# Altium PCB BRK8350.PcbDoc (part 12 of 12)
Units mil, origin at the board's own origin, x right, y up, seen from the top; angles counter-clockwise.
Board outline 9448.82 x 5905.51 mil, 8 copper layers (L1-TOP, L2-GND, L3-SIG, L4-GND, L5-PWR, L6-PWR, L7-GND, L8-BOT), stack 57.69 mil thick; 288 components, 543 nets, 1891 pads, 2032 vias.
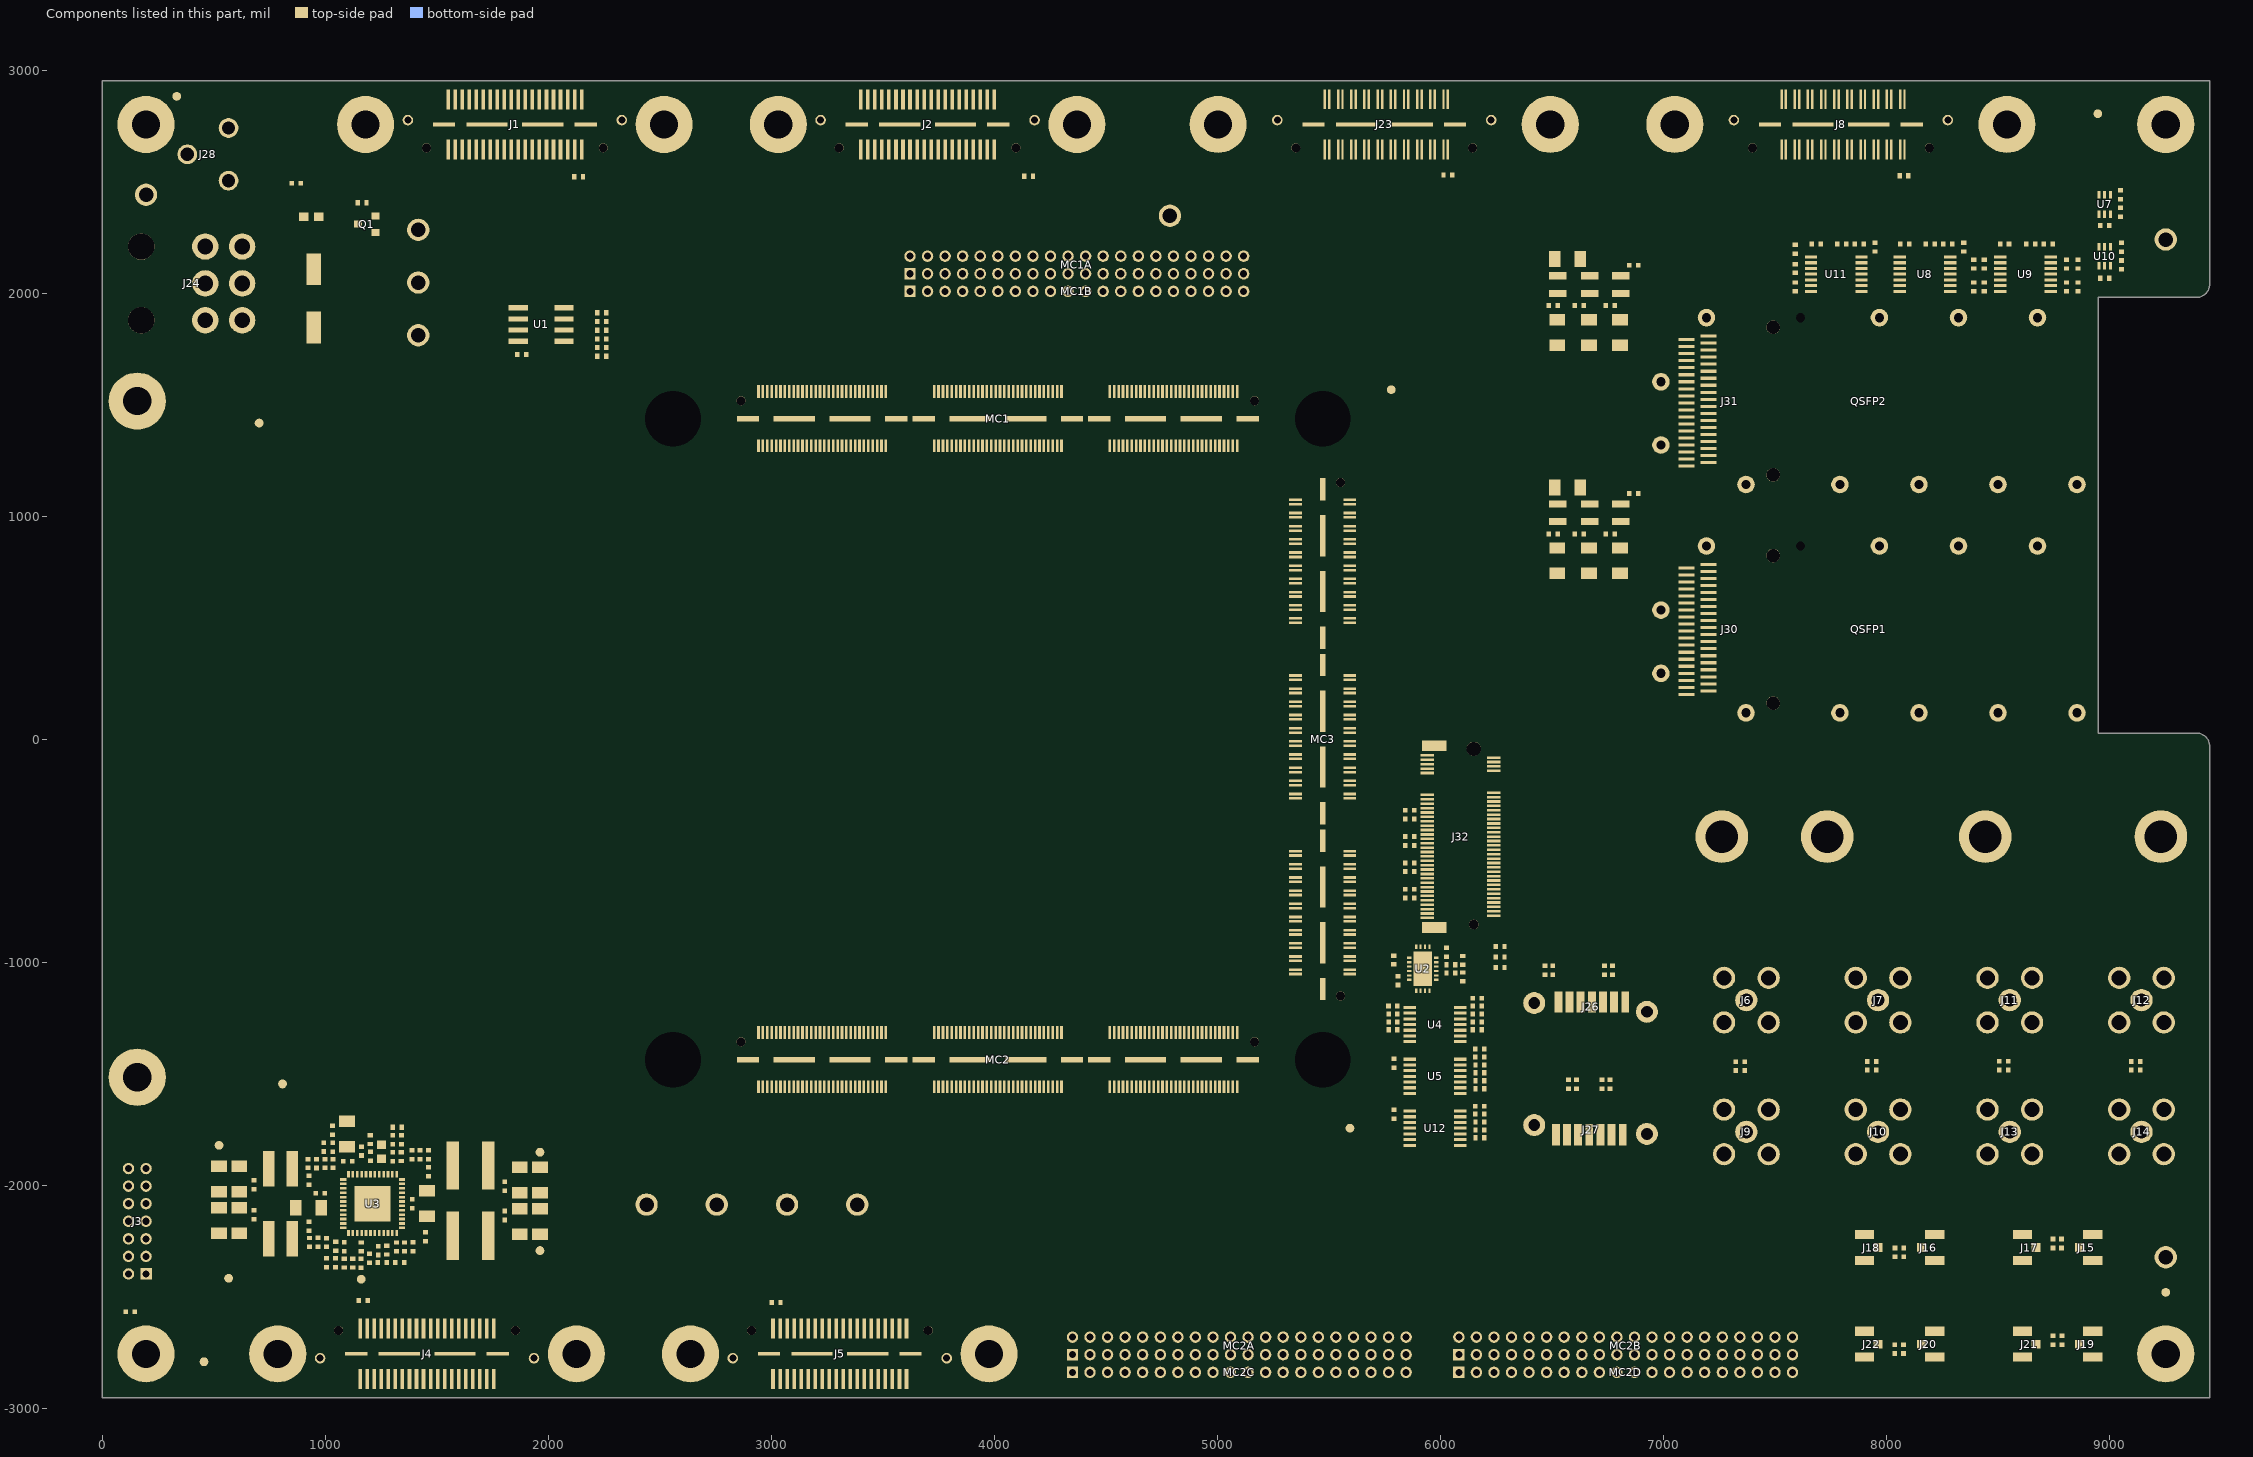
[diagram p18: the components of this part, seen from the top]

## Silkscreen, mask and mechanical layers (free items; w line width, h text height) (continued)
Fab Notes:
  drawing of 156 lines, arcs and shapes, not listed
  text "NOTES: /  / 1. MATERIAL: /    IT-180A or equivalent /    Surface finish: ENIG /    Overall thickness: 93 mils +/-10% /  / 2. Fabricate to IPC-6012 (latest revision), Class 2 /  / 3. SOLDER RESIST: Glossy blue LPI applied over bare copper or gold/nickel plating /  / 4. SILKSCREEN: White /  / 5. LOT CODE IDENTIFICATION: /    Supplier must add identifier and lot code date to silkscreen. /    LOT CODE DATE FORMAT: YYWW (YY = 2-digit year, WW = 2-digit week) /  / 6. Drill sizes are finished size after plating /  / 7. 100% electrical bare board test required for continuity /  / 8. IMPEDANCE CONTROL: /    See Layer Stackup Table on this drawing and refer to '.Part_Number'-PCBStackup.pdf /  / 9. PANELIZATION: /    1 pieces per array /    Tab routing required. Tab locations indicated by ::: (see Dimensions Gerber layer) /    OUTLINE DIMENSION TOLERANCE: +/-0.127 mm /    0.25-inch rails on all sides /  / 10. POFV: All 10-mil diameter vias must be filled using non-conductive epoxy and plated over. /  / 11. ROHS: Fabricate to meet EU RoHS directive. Supplier must add lead-free marking in silkscreen. /  / 12. UL: Supplier must add UL certification marking (94V-0) in silkscreen. /  / 13. Remove all non-functional pads from internal layers" at -129.92,4185.04 h38
  text "LAYER STACKUP TABLE" at 9901.57,3334.65 h50
  text "S" at 12745.09,3247.32 h68.37
  text "i" at 12772.5,3247.32 h68.37
  text "n" at 12788.16,3247.32 h68.37
  text "g" at 12819.49,3247.32 h68.37
  text "l" at 12846.9,3247.32 h68.37
  text "e" at 12862.57,3247.32 h68.37
  text "-" at 12893.89,3247.32 h68.37
  text "E" at 12913.47,3247.32 h68.37
  text "n" at 12940.88,3247.32 h68.37
  text "d" at 12972.21,3247.32 h68.37
  text "e" at 13003.54,3247.32 h68.37
  text "d" at 13034.87,3247.32 h68.37
  text "D" at 13870.76,3247.32 h68.37
  text "i" at 13906,3247.32 h68.37
  text "f" at 13921.66,3247.32 h68.37
  text "f" at 13941.24,3247.32 h68.37
  text "e" at 13960.82,3247.32 h68.37
  text "r" at 13992.15,3247.32 h68.37
  text "e" at 14011.73,3247.32 h68.37
  text "n" at 14043.06,3247.32 h68.37
  text "t" at 14074.39,3247.32 h68.37
  text "i" at 14093.97,3247.32 h68.37
  text "a" at 14109.63,3247.32 h68.37
  text "l" at 14137.04,3247.32 h68.37
  text "D" at 14195.17,3247.32 h68.37
  text "i" at 14230.41,3247.32 h68.37
  text "f" at 14246.08,3247.32 h68.37
  text "f" at 14265.66,3247.32 h68.37
  text "e" at 14285.24,3247.32 h68.37
  text "r" at 14316.56,3247.32 h68.37
  text "e" at 14336.14,3247.32 h68.37
  text "n" at 14367.47,3247.32 h68.37
  text "t" at 14398.8,3247.32 h68.37
  text "i" at 14418.38,3247.32 h68.37
  text "a" at 14434.04,3247.32 h68.37
  text "l" at 14461.45,3247.32 h68.37
  text "M" at 12022,3171.76 h68.37
  text "a" at 12072.91,3171.76 h68.37
  text "t" at 12104.24,3171.76 h68.37
  text "e" at 12123.81,3171.76 h68.37
  text "r" at 12159.06,3171.76 h68.37
  text "i" at 12182.55,3171.76 h68.37
  text "a" at 12198.22,3171.76 h68.37
  text "l" at 12229.55,3171.76 h68.37
  text "T" at 12842.8,3169 h68.37
  text "r" at 12870.21,3169 h68.37
  text "a" at 12889.79,3169 h68.37
  text "c" at 12917.2,3169 h68.37
  text "e" at 12940.7,3169 h68.37
  text "S" at 13112.49,3169 h68.37
  text "i" at 13139.9,3169 h68.37
  text "n" at 13155.57,3169 h68.37
  text "g" at 13186.9,3169 h68.37
  text "l" at 13214.31,3169 h68.37
  text "e" at 13229.97,3169 h68.37
  text "-" at 13261.3,3169 h68.37
  text "E" at 13280.88,3169 h68.37
  text "n" at 13308.29,3169 h68.37
  text "d" at 13339.62,3169 h68.37
  text "e" at 13370.94,3169 h68.37
  text "d" at 13402.27,3169 h68.37
  text "T" at 13948.93,3169 h68.37
  text "r" at 13976.34,3169 h68.37
  text "a" at 13995.92,3169 h68.37
  text "c" at 14023.33,3169 h68.37
  text "e" at 14046.83,3169 h68.37
  text "T" at 14269.43,3169 h68.37
  text "r" at 14296.84,3169 h68.37
  text "a" at 14316.42,3169 h68.37
  text "c" at 14343.83,3169 h68.37
  text "e" at 14367.33,3169 h68.37
  text "G" at 10626.64,3093.44 h68.37
  text "e" at 10673.63,3093.44 h68.37
  text "r" at 10708.87,3093.44 h68.37
  text "b" at 10732.37,3093.44 h68.37
  text "e" at 10767.61,3093.44 h68.37
  text "r" at 10802.86,3093.44 h68.37
  text "M" at 11263.74,3093.44 h68.37
  text "a" at 11314.64,3093.44 h68.37
  text "t" at 11345.97,3093.44 h68.37
  text "e" at 11365.55,3093.44 h68.37
  text "r" at 11400.79,3093.44 h68.37
  text "i" at 11424.29,3093.44 h68.37
  text "a" at 11439.95,3093.44 h68.37
  text "l" at 11471.28,3093.44 h68.37
  text "M" at 11646.78,3093.44 h68.37
  text "a" at 11697.68,3093.44 h68.37
  text "t" at 11729.01,3093.44 h68.37
  text "e" at 11748.59,3093.44 h68.37
  text "r" at 11783.83,3093.44 h68.37
  text "i" at 11807.33,3093.44 h68.37
  text "a" at 11822.99,3093.44 h68.37
  text "l" at 11854.32,3093.44 h68.37
  text "E" at 11885.65,3093.44 h68.37
  text "r" at 11924.81,3093.44 h68.37
  text "T" at 11990.73,3093.44 h68.37
  text "h" at 12029.89,3093.44 h68.37
  text "i" at 12065.13,3093.44 h68.37
  text "c" at 12080.8,3093.44 h68.37
  text "k" at 12112.13,3093.44 h68.37
  text "n" at 12143.45,3093.44 h68.37
  text "e" at 12178.7,3093.44 h68.37
  text "s" at 12213.94,3093.44 h68.37
  text "s" at 12245.27,3093.44 h68.37
  text "C" at 12408.95,3090.68 h68.37
  text "o" at 12440.28,3090.68 h68.37
  text "p" at 12471.6,3090.68 h68.37
  text "p" at 12502.93,3090.68 h68.37
  text "e" at 12534.26,3090.68 h68.37
  text "r" at 12565.59,3090.68 h68.37
  text "I" at 12772.45,3090.68 h68.37
  text "m" at 12788.11,3090.68 h68.37
  text "p" at 12835.1,3090.68 h68.37
  text "e" at 12866.43,3090.68 h68.37
  text "d" at 12897.76,3090.68 h68.37
  text "a" at 12929.08,3090.68 h68.37
  text "n" at 12956.5,3090.68 h68.37
  text "c" at 12987.82,3090.68 h68.37
  text "e" at 13011.32,3090.68 h68.37
  text "T" at 13128.13,3090.68 h68.37
  text "r" at 13155.54,3090.68 h68.37
  text "a" at 13175.12,3090.68 h68.37
  text "c" at 13202.53,3090.68 h68.37
  text "e" at 13226.03,3090.68 h68.37
  text "W" at 13269.1,3090.68 h68.37
  text "i" at 13323.92,3090.68 h68.37
  text "d" at 13339.59,3090.68 h68.37
  text "t" at 13370.92,3090.68 h68.37
  text "h" at 13390.5,3090.68 h68.37
  text "I" at 13878.57,3090.68 h68.37
  text "m" at 13894.24,3090.68 h68.37
  text "p" at 13941.23,3090.68 h68.37
  text "e" at 13972.56,3090.68 h68.37
  text "d" at 14003.88,3090.68 h68.37
  text "a" at 14035.21,3090.68 h68.37
  text "n" at 14062.62,3090.68 h68.37
  text "c" at 14093.95,3090.68 h68.37
  text "e" at 14117.45,3090.68 h68.37
  text "W" at 14175.63,3090.68 h68.37
  text "i" at 14230.45,3090.68 h68.37
  text "d" at 14246.11,3090.68 h68.37
  text "t" at 14277.44,3090.68 h68.37
  text "h" at 14297.02,3090.68 h68.37
  text "/" at 14328.35,3090.68 h68.37
  text "S" at 14351.84,3090.68 h68.37
  text "p" at 14379.25,3090.68 h68.37
  text "a" at 14410.58,3090.68 h68.37
  text "c" at 14437.99,3090.68 h68.37
  text "e" at 14461.49,3090.68 h68.37
  text "L" at 9876.19,3015.12 h68.37
  text "a" at 9911.44,3015.12 h68.37
  text "y" at 9942.76,3015.12 h68.37
  text "e" at 9970.17,3015.12 h68.37
  text "r" at 10005.42,3015.12 h68.37
  text "L" at 10071.62,3015.12 h68.37
  text "a" at 10106.86,3015.12 h68.37
  text "y" at 10138.19,3015.12 h68.37
  text "e" at 10165.6,3015.12 h68.37
  text "r" at 10200.85,3015.12 h68.37
  text "N" at 10240.01,3015.12 h68.37
  text "a" at 10283.08,3015.12 h68.37
  text "m" at 10314.41,3015.12 h68.37
  text "e" at 10361.4,3015.12 h68.37
  text "L" at 10626.64,3015.12 h68.37
  text "a" at 10661.88,3015.12 h68.37
  text "y" at 10693.21,3015.12 h68.37
  text "e" at 10720.62,3015.12 h68.37
  text "r" at 10755.86,3015.12 h68.37
  text "M" at 10861.15,3015.12 h68.37
  text "a" at 10912.06,3015.12 h68.37
  text "t" at 10943.39,3015.12 h68.37
  text "e" at 10962.97,3015.12 h68.37
  text "r" at 10998.21,3015.12 h68.37
  text "i" at 11021.71,3015.12 h68.37
  text "a" at 11037.37,3015.12 h68.37
  text "l" at 11068.7,3015.12 h68.37
  text "T" at 11100.03,3015.12 h68.37
  text "y" at 11139.19,3015.12 h68.37
  text "p" at 11166.6,3015.12 h68.37
  text "e" at 11201.84,3015.12 h68.37
  text "C" at 11263.74,3015.12 h68.37
  text "o" at 11306.81,3015.12 h68.37
  text "n" at 11342.06,3015.12 h68.37
  text "s" at 11377.3,3015.12 h68.37
  text "t" at 11408.63,3015.12 h68.37
  text "r" at 11428.21,3015.12 h68.37
  text "u" at 11451.7,3015.12 h68.37
  text "c" at 11486.95,3015.12 h68.37
  text "t" at 11518.27,3015.12 h68.37
  text "i" at 11537.85,3015.12 h68.37
  text "o" at 11553.52,3015.12 h68.37
  text "n" at 11588.76,3015.12 h68.37
  text "(" at 11693.68,3015.12 h68.37
  text "1" at 11713.26,3015.12 h68.37
  text "G" at 11760.25,3015.12 h68.37
  text "H" at 11807.24,3015.12 h68.37
  text "z" at 11850.32,3015.12 h68.37
  text ")" at 11881.65,3015.12 h68.37
  text "(" at 12076.72,3015.12 h68.37
  text "m" at 12096.3,3015.12 h68.37
  text "i" at 12143.29,3015.12 h68.37
  text "l" at 12158.96,3015.12 h68.37
  text ")" at 12174.62,3015.12 h68.37
  text "W" at 12354.23,3012.36 h68.37
  text "e" at 12409.05,3012.36 h68.37
  text "i" at 12440.38,3012.36 h68.37
  text "g" at 12456.04,3012.36 h68.37
  text "h" at 12483.46,3012.36 h68.37
  text "t" at 12514.78,3012.36 h68.37
  text "(" at 12546.11,3012.36 h68.37
  text "o" at 12565.69,3012.36 h68.37
  text "z" at 12597.02,3012.36 h68.37
  text ")" at 12620.51,3012.36 h68.37
  text "(" at 12819.35,3012.36 h68.37
  text "o" at 12838.93,3012.36 h68.37
  text "h" at 12870.26,3012.36 h68.37
  text "m" at 12901.58,3012.36 h68.37
  text "s" at 12948.58,3012.36 h68.37
  text ")" at 12972.07,3012.36 h68.37
  text "(" at 13202.39,3012.36 h68.37
  text "m" at 13221.97,3012.36 h68.37
  text "i" at 13268.96,3012.36 h68.37
  text "l" at 13284.62,3012.36 h68.37
  text "s" at 13300.29,3012.36 h68.37
  text ")" at 13323.78,3012.36 h68.37
  text "R" at 13511.17,3012.36 h68.37
  text "e" at 13542.5,3012.36 h68.37
  text "f" at 13573.82,3012.36 h68.37
  text "e" at 13593.4,3012.36 h68.37
  text "r" at 13624.73,3012.36 h68.37
  text "e" at 13644.31,3012.36 h68.37
  text "n" at 13675.64,3012.36 h68.37
  text "c" at 13706.96,3012.36 h68.37
  text "e" at 13730.46,3012.36 h68.37
  text "(" at 13925.48,3012.36 h68.37
  text "o" at 13945.06,3012.36 h68.37
  text "h" at 13976.38,3012.36 h68.37
  text "m" at 14007.71,3012.36 h68.37
  text "s" at 14054.7,3012.36 h68.37
  text ")" at 14078.2,3012.36 h68.37
  text "(" at 14265.52,3012.36 h68.37
  text "m" at 14285.1,3012.36 h68.37
  text "i" at 14332.09,3012.36 h68.37
  text "l" at 14347.76,3012.36 h68.37
  text "s" at 14363.42,3012.36 h68.37
  text ")" at 14386.92,3012.36 h68.37
  text "R" at 14562.57,3012.36 h68.37
  text "e" at 14593.9,3012.36 h68.37
  text "f" at 14625.23,3012.36 h68.37
  text "e" at 14644.81,3012.36 h68.37
  text "r" at 14676.14,3012.36 h68.37
  text "e" at 14695.72,3012.36 h68.37
  text "n" at 14727.04,3012.36 h68.37
  text "c" at 14758.37,3012.36 h68.37
  text "e" at 14781.87,3012.36 h68.37
  text "O" at 10071.62,2901.56 h64.57
  text "v" at 10118.61,2901.56 h64.57
  text "e" at 10146.02,2901.56 h64.57
  text "r" at 10177.35,2901.56 h64.57
  text "l" at 10196.93,2901.56 h64.57
  text "a" at 10208.68,2901.56 h64.57
  text "y" at 10240.01,2901.53 h64.57
  text "T" at 10283.08,2901.56 h64.57
  text "o" at 10318.33,2901.56 h64.57
  text "p" at 10349.65,2901.53 h64.57
  text "G" at 10626.64,2901.56 h64.57
  text "T" at 10669.71,2901.56 h64.57
  text "O" at 10704.96,2901.56 h64.57
  text "S" at 10861.15,2901.56 h64.57
  text "i" at 10900.31,2901.56 h64.57
  text "l" at 10912.06,2901.56 h64.57
  text "k" at 10923.81,2901.56 h64.57
  text "s" at 10951.22,2901.56 h64.57
  text "c" at 10982.55,2901.56 h64.57
  text "r" at 11013.88,2901.56 h64.57
  text "e" at 11033.45,2901.56 h64.57
  text "e" at 11064.78,2901.56 h64.57
  text "n" at 11096.11,2901.56 h64.57
  text "S" at 10071.62,2823.24 h64.57
  text "o" at 10110.78,2823.24 h64.57
  text "l" at 10142.11,2823.24 h64.57
  text "d" at 10153.86,2823.24 h64.57
  text "e" at 10185.18,2823.24 h64.57
  text "r" at 10216.51,2823.24 h64.57
  text "M" at 10251.75,2823.24 h64.57
  text "a" at 10294.83,2823.24 h64.57
  text "s" at 10326.16,2823.24 h64.57
  text "k" at 10357.48,2823.24 h64.57
  text "T" at 10400.56,2823.24 h64.57
  text "o" at 10435.8,2823.24 h64.57
  text "p" at 10467.13,2823.21 h64.57
  text "G" at 10626.64,2823.24 h64.57
  text "T" at 10669.71,2823.24 h64.57
  text "S" at 10704.96,2823.24 h64.57
  text "S" at 10861.15,2823.24 h64.57
  text "o" at 10900.31,2823.24 h64.57
  text "l" at 10931.64,2823.24 h64.57
  text "d" at 10943.39,2823.24 h64.57
  text "e" at 10974.72,2823.24 h64.57
  text "r" at 11006.04,2823.24 h64.57
  text "R" at 11041.29,2823.24 h64.57
  text "e" at 11084.36,2823.24 h64.57
  text "s" at 11115.69,2823.24 h64.57
  text "i" at 11147.02,2823.24 h64.57
  text "s" at 11158.76,2823.24 h64.57
  text "t" at 11190.09,2823.24 h64.57
  text "3" at 11764.03,2820.48 h68.37
  text "." at 11791.45,2820.48 h68.37
  text "5" at 11807.11,2820.48 h68.37
  text "1" at 9876.19,2744.92 h64.57
  text "L" at 10071.62,2744.92 h64.57
  text "1" at 10102.95,2744.92 h64.57
  text "-" at 10134.28,2744.96 h64.57
  text "T" at 10153.86,2744.92 h64.57
  text "O" at 10189.1,2744.92 h64.57
  text "P" at 10236.09,2744.92 h64.57
  text "G" at 10626.64,2744.92 h64.57
  text "T" at 10669.71,2744.92 h64.57
  text "L" at 10704.96,2744.92 h64.57
  text "C" at 10861.15,2744.92 h64.57
  text "o" at 10904.23,2744.92 h64.57
  text "p" at 10935.56,2744.89 h64.57
  text "p" at 10966.88,2744.89 h64.57
  text "e" at 10998.21,2744.92 h64.57
  text "r" at 11029.54,2744.92 h64.57
  text "0" at 12100.17,2742.16 h68.37
  text "." at 12127.58,2742.16 h68.37
  text "7" at 12143.25,2742.16 h68.37
  text "1" at 12350.32,2742.16 h68.37
  text "/" at 12377.73,2742.16 h68.37
  text "3" at 12401.23,2742.16 h68.37
  text "+" at 12440.39,2742.16 h68.37
  text "p" at 12479.55,2742.16 h68.37
  text "l" at 12510.87,2742.16 h68.37
  text "a" at 12526.54,2742.16 h68.37
  text "t" at 12553.95,2742.16 h68.37
  text "i" at 12573.53,2742.16 h68.37
  text "n" at 12589.19,2742.16 h68.37
  text "g" at 12620.52,2742.16 h68.37
  text "5" at 12881.89,2742.16 h68.37
  text "0" at 12909.3,2742.16 h68.37
  text "4" at 13225.84,2742.16 h68.37
  text "." at 13253.25,2742.16 h68.37
  text "5" at 13268.92,2742.16 h68.37
  text "0" at 13296.33,2742.16 h68.37
  text "L" at 13612.79,2742.16 h68.37
  text "2" at 13636.29,2742.16 h68.37
  text "1" at 13972.38,2742.16 h68.37
  text "0" at 13999.79,2742.16 h68.37
  text "0" at 14027.2,2742.16 h68.37
  text "4" at 14214.71,2742.16 h68.37
  text "." at 14242.12,2742.16 h68.37
  text "2" at 14257.79,2742.16 h68.37
  text "0" at 14285.2,2742.16 h68.37
  text "/" at 14324.36,2742.16 h68.37
  text "8" at 14359.6,2742.16 h68.37
  text "." at 14387.01,2742.16 h68.37
  text "4" at 14402.68,2742.16 h68.37
  text "0" at 14430.09,2742.16 h68.37
  text "L" at 14664.2,2742.16 h68.37
  text "2" at 14687.69,2742.16 h68.37
  text "P" at 10861.15,2666.61 h64.57
  text "r" at 10900.31,2666.61 h64.57
  text "e" at 10919.89,2666.6 h64.57
  text "p" at 10951.22,2666.57 h64.57
  text "r" at 10982.55,2666.61 h64.57
  text "e" at 11002.13,2666.6 h64.57
  text "g" at 11033.45,2666.57 h64.57
  text "P" at 11263.74,2663.84 h68.37
  text "P" at 11295.06,2663.84 h68.37
  text "(" at 11326.39,2663.84 h68.37
  text "1" at 11345.97,2663.84 h68.37
  text "0" at 11373.38,2663.84 h68.37
  text "8" at 11400.79,2663.84 h68.37
  text "0" at 11428.21,2663.84 h68.37
  text ")" at 11455.62,2663.84 h68.37
  text "R" at 11475.2,2663.84 h68.37
  text "C" at 11506.52,2663.84 h68.37
  text "7" at 11537.85,2663.84 h68.37
  text "1" at 11565.26,2663.84 h68.37
  text "3" at 11764.03,2663.84 h68.37
  text "." at 11791.45,2663.84 h68.37
  text "9" at 11807.11,2663.84 h68.37
  text "3" at 12088.45,2663.84 h68.37
  text "." at 12115.86,2663.84 h68.37
  text "7" at 12131.52,2663.84 h68.37
  text "4" at 12158.93,2663.84 h68.37
  text "2" at 9876.19,2588.29 h64.57
  text "L" at 10071.62,2588.29 h64.57
  text "2" at 10102.95,2588.29 h64.57
  text "-" at 10134.28,2588.32 h64.57
  text "G" at 10153.86,2588.28 h64.57
  text "N" at 10196.93,2588.29 h64.57
  text "D" at 10236.09,2588.29 h64.57
  text "G" at 10626.64,2588.28 h64.57
  text "1" at 10669.71,2588.29 h64.57
  text "C" at 10861.15,2588.28 h64.57
  text "o" at 10904.23,2588.29 h64.57
  text "p" at 10935.56,2588.25 h64.57
  text "p" at 10966.88,2588.25 h64.57
  text "e" at 10998.21,2588.29 h64.57
  text "r" at 11029.54,2588.29 h64.57
  text "0" at 12100.17,2585.53 h68.37
  text "." at 12127.58,2585.53 h68.37
  text "7" at 12143.25,2585.53 h68.37
  text "1" at 12459.76,2585.53 h68.37
  text "/" at 12487.17,2585.52 h68.37
  text "2" at 12510.67,2585.53 h68.37
  text "C" at 10861.15,2509.97 h64.57
  text "o" at 10904.23,2509.97 h64.57
  text "r" at 10935.56,2509.97 h64.57
  text "e" at 10955.14,2509.97 h64.57
  text "2" at 11263.74,2507.21 h68.37
  text "*" at 11291.15,2507.21 h68.37
  text "7" at 11318.56,2507.21 h68.37
  text "6" at 11345.97,2507.21 h68.37
  text "2" at 11373.38,2507.21 h68.37
  text "8" at 11400.79,2507.21 h68.37
  text "(" at 11439.95,2507.21 h68.37
  text "R" at 11459.53,2507.21 h68.37
  text "C" at 11490.86,2507.21 h68.37
  text "5" at 11522.19,2507.21 h68.37
  text "0" at 11549.6,2507.21 h68.37
  text ")" at 11577.01,2507.21 h68.37
  text "4" at 11764.03,2507.21 h68.37
  text "." at 11791.45,2507.21 h68.37
  text "6" at 11807.11,2507.21 h68.37
  text "1" at 12107.99,2507.21 h68.37
  text "6" at 12135.4,2507.21 h68.37
  text "3" at 9876.19,2431.65 h64.57
  text "L" at 10071.62,2431.65 h64.57
  text "3" at 10102.95,2431.65 h64.57
  text "-" at 10134.28,2431.68 h64.57
  text "S" at 10153.86,2431.65 h64.57
  text "I" at 10193.02,2431.65 h64.57
  text "G" at 10204.76,2431.65 h64.57
  text "G" at 10626.64,2431.65 h64.57
  text "2" at 10669.71,2431.65 h64.57
  text "C" at 10861.15,2431.65 h64.57
  text "o" at 10904.23,2431.65 h64.57
  text "p" at 10935.56,2431.62 h64.57
  text "p" at 10966.88,2431.62 h64.57
  text "e" at 10998.21,2431.65 h64.57
  text "r" at 11029.54,2431.65 h64.57
  text "0" at 12100.17,2428.89 h68.37
  text "." at 12127.58,2428.89 h68.37
  text "7" at 12143.25,2428.89 h68.37
  text "1" at 12459.76,2428.89 h68.37
  text "/" at 12487.17,2428.89 h68.37
  text "2" at 12510.67,2428.89 h68.37
  text "5" at 12881.89,2428.89 h68.37
  text "0" at 12909.3,2428.89 h68.37
  text "4" at 13225.84,2428.89 h68.37
  text "." at 13253.25,2428.89 h68.37
  text "6" at 13268.92,2428.89 h68.37
  text "0" at 13296.33,2428.89 h68.37
  text "L" at 13573.71,2428.89 h68.37
  text "2" at 13597.2,2428.89 h68.37
  text "/" at 13624.61,2428.89 h68.37
  text "L" at 13648.11,2428.89 h68.37
  text "4" at 13671.6,2428.89 h68.37
  text "1" at 13972.38,2428.89 h68.37
  text "0" at 13999.79,2428.89 h68.37
  text "0" at 14027.2,2428.89 h68.37
  text "4" at 14214.71,2428.89 h68.37
  text "." at 14242.12,2428.89 h68.37
  text "2" at 14257.79,2428.89 h68.37
  text "5" at 14285.2,2428.89 h68.37
  text "/" at 14324.36,2428.89 h68.37
  text "8" at 14359.6,2428.89 h68.37
  text "." at 14387.01,2428.89 h68.37
  text "4" at 14402.68,2428.89 h68.37
  text "0" at 14430.09,2428.89 h68.37
  text "L" at 14625.11,2428.89 h68.37
  text "2" at 14648.61,2428.89 h68.37
  text "/" at 14676.02,2428.89 h68.37
  text "L" at 14699.51,2428.89 h68.37
  text "4" at 14723.01,2428.89 h68.37
  text "P" at 10861.15,2353.33 h64.57
  text "r" at 10900.31,2353.33 h64.57
  text "e" at 10919.89,2353.33 h64.57
  text "p" at 10951.22,2353.3 h64.57
  text "r" at 10982.55,2353.33 h64.57
  text "e" at 11002.13,2353.33 h64.57
  text "g" at 11033.45,2353.3 h64.57
  text "P" at 11263.74,2350.57 h68.37
  text "P" at 11295.06,2350.57 h68.37
  text "(" at 11326.39,2350.57 h68.37
  text "1" at 11345.97,2350.57 h68.37
  text "0" at 11373.38,2350.57 h68.37
  text "8" at 11400.79,2350.57 h68.37
  text "0" at 11428.21,2350.57 h68.37
  text ")" at 11455.62,2350.57 h68.37
  text "R" at 11475.2,2350.57 h68.37
  text "C" at 11506.52,2350.57 h68.37
  text "7" at 11537.85,2350.57 h68.37
  text "1" at 11565.26,2350.57 h68.37
  text "3" at 11764.03,2350.57 h68.37
  text "." at 11791.45,2350.57 h68.37
  text "9" at 11807.11,2350.57 h68.37
  text "3" at 12088.45,2350.57 h68.37
  text "." at 12115.86,2350.57 h68.37
  text "7" at 12131.52,2350.57 h68.37
  text "4" at 12158.93,2350.57 h68.37
  text "4" at 9876.19,2275.01 h64.57
  text "L" at 10071.62,2275.01 h64.57
  text "4" at 10102.95,2275.01 h64.57
  text "-" at 10134.28,2275.05 h64.57
  text "G" at 10153.86,2275.01 h64.57
  text "N" at 10196.93,2275.01 h64.57
  text "D" at 10236.09,2275.01 h64.57
  text "G" at 10626.64,2275.01 h64.57
  text "3" at 10669.71,2275.01 h64.57
  text "C" at 10861.15,2275.01 h64.57
  text "o" at 10904.23,2275.01 h64.57
  text "p" at 10935.56,2274.98 h64.57
  text "p" at 10966.88,2274.98 h64.57
  text "e" at 10998.21,2275.01 h64.57
  text "r" at 11029.54,2275.01 h64.57
  text "0" at 12100.17,2272.25 h68.37
  text "." at 12127.58,2272.25 h68.37
  text "7" at 12143.25,2272.25 h68.37
  text "1" at 12459.76,2272.25 h68.37
  text "/" at 12487.17,2272.25 h68.37
  text "2" at 12510.67,2272.25 h68.37
  text "C" at 10861.15,2196.69 h64.57
  text "o" at 10904.23,2196.69 h64.57
  text "r" at 10935.56,2196.69 h64.57
  text "e" at 10955.14,2196.69 h64.57
  text "2" at 11263.74,2193.93 h68.37
  text "*" at 11291.15,2193.94 h68.37
  text "7" at 11318.56,2193.93 h68.37
  text "6" at 11345.97,2193.93 h68.37
  text "2" at 11373.38,2193.93 h68.37
  text "8" at 11400.79,2193.93 h68.37
  text "(" at 11439.95,2193.93 h68.37
  text "R" at 11459.53,2193.93 h68.37
  text "C" at 11490.86,2193.93 h68.37
  text "5" at 11522.19,2193.93 h68.37
  text "0" at 11549.6,2193.93 h68.37
  text ")" at 11577.01,2193.93 h68.37
  text "4" at 11764.03,2193.93 h68.37
  text "." at 11791.45,2193.93 h68.37
  text "6" at 11807.11,2193.93 h68.37
  text "3" at 12107.99,2193.93 h68.37
  text "9" at 12135.4,2193.93 h68.37
  text "5" at 9876.19,2118.37 h64.57
  text "L" at 10071.62,2118.37 h64.57
  text "5" at 10102.95,2118.37 h64.57
  text "-" at 10134.28,2118.41 h64.57
  text "P" at 10153.86,2118.37 h64.57
  text "W" at 10193.02,2118.37 h64.57
  text "R" at 10251.75,2118.37 h64.57
  text "G" at 10626.64,2118.37 h64.57
  text "4" at 10669.71,2118.37 h64.57
  text "C" at 10861.15,2118.37 h64.57
  text "o" at 10904.23,2118.37 h64.57
  text "p" at 10935.56,2118.34 h64.57
  text "p" at 10966.88,2118.34 h64.57
  text "e" at 10998.21,2118.37 h64.57
  text "r" at 11029.54,2118.37 h64.57
  text "0" at 12100.17,2115.61 h68.37
  text "." at 12127.58,2115.61 h68.37
  text "7" at 12143.25,2115.61 h68.37
  text "1" at 12459.76,2115.61 h68.37
  text "/" at 12487.17,2115.61 h68.37
  text "2" at 12510.67,2115.61 h68.37
  text "P" at 10861.15,2040.06 h64.57
  text "r" at 10900.31,2040.06 h64.57
  text "e" at 10919.89,2040.05 h64.57
  text "p" at 10951.22,2040.02 h64.57
  text "r" at 10982.55,2040.06 h64.57
  text "e" at 11002.13,2040.05 h64.57
  text "g" at 11033.45,2040.02 h64.57
  text "P" at 11263.74,2037.3 h68.37
  text "P" at 11295.06,2037.3 h68.37
  text "(" at 11326.39,2037.29 h68.37
  text "1" at 11345.97,2037.3 h68.37
  text "0" at 11373.38,2037.3 h68.37
  text "8" at 11400.79,2037.3 h68.37
  text "0" at 11428.21,2037.3 h68.37
  text ")" at 11455.62,2037.29 h68.37
  text "R" at 11475.2,2037.3 h68.37
  text "C" at 11506.52,2037.3 h68.37
  text "7" at 11537.85,2037.3 h68.37
  text "1" at 11565.26,2037.3 h68.37
  text "3" at 11764.03,2037.3 h68.37
  text "." at 11791.45,2037.3 h68.37
  text "9" at 11807.11,2037.3 h68.37
  text "3" at 12088.45,2037.3 h68.37
  text "." at 12115.86,2037.3 h68.37
  text "7" at 12131.52,2037.3 h68.37
  text "4" at 12158.93,2037.3 h68.37
  text "6" at 9876.19,1961.74 h64.57
  text "L" at 10071.62,1961.74 h64.57
  text "6" at 10102.95,1961.74 h64.57
  text "-" at 10134.28,1961.77 h64.57
  text "P" at 10153.86,1961.74 h64.57
  text "W" at 10193.02,1961.74 h64.57
  text "R" at 10251.75,1961.74 h64.57
  text "G" at 10626.64,1961.74 h64.57
  text "5" at 10669.71,1961.74 h64.57
  text "C" at 10861.15,1961.74 h64.57
  text "o" at 10904.23,1961.74 h64.57
  text "p" at 10935.56,1961.7 h64.57
  text "p" at 10966.88,1961.7 h64.57
  text "e" at 10998.21,1961.74 h64.57
  text "r" at 11029.54,1961.74 h64.57
  text "0" at 12100.17,1958.98 h68.37
  text "." at 12127.58,1958.98 h68.37
  text "7" at 12143.25,1958.98 h68.37
  text "1" at 12459.76,1958.98 h68.37
  text "/" at 12487.17,1958.97 h68.37
  text "2" at 12510.67,1958.98 h68.37
  text "C" at 10861.15,1883.42 h64.57
  text "o" at 10904.23,1883.42 h64.57
  text "r" at 10935.56,1883.42 h64.57
  text "e" at 10955.14,1883.42 h64.57
  text "2" at 11263.74,1880.66 h68.37
  text "*" at 11291.15,1880.66 h68.37
  text "7" at 11318.56,1880.66 h68.37
  text "6" at 11345.97,1880.66 h68.37
  text "2" at 11373.38,1880.66 h68.37
  text "8" at 11400.79,1880.66 h68.37
  text "(" at 11439.95,1880.66 h68.37
  text "R" at 11459.53,1880.66 h68.37
  text "C" at 11490.86,1880.66 h68.37
  text "5" at 11522.19,1880.66 h68.37
  text "0" at 11549.6,1880.66 h68.37
  text ")" at 11577.01,1880.66 h68.37
  text "4" at 11764.03,1880.66 h68.37
  text "." at 11791.45,1880.66 h68.37
  text "6" at 11807.11,1880.66 h68.37
  text "1" at 12107.99,1880.66 h68.37
  text "6" at 12135.4,1880.66 h68.37
  text "7" at 9876.19,1805.1 h64.57
  text "L" at 10071.62,1805.1 h64.57
  text "7" at 10102.95,1805.1 h64.57
  text "-" at 10134.28,1805.13 h64.57
  text "G" at 10153.86,1805.1 h64.57
  text "N" at 10196.93,1805.1 h64.57
  text "D" at 10236.09,1805.1 h64.57
  text "G" at 10626.64,1805.1 h64.57
  text "6" at 10669.71,1805.1 h64.57
  text "C" at 10861.15,1805.1 h64.57
  text "o" at 10904.23,1805.1 h64.57
  text "p" at 10935.56,1805.07 h64.57
  text "p" at 10966.88,1805.07 h64.57
  text "e" at 10998.21,1805.1 h64.57
  text "r" at 11029.54,1805.1 h64.57
  text "0" at 12100.17,1802.34 h68.37
  text "." at 12127.58,1802.34 h68.37
  text "7" at 12143.25,1802.34 h68.37
  text "1" at 12459.76,1802.34 h68.37
  text "/" at 12487.17,1802.34 h68.37
  text "2" at 12510.67,1802.34 h68.37
  text "P" at 10861.15,1726.78 h64.57
  text "r" at 10900.31,1726.78 h64.57
  text "e" at 10919.89,1726.78 h64.57
  text "p" at 10951.22,1726.75 h64.57
  text "r" at 10982.55,1726.78 h64.57
  text "e" at 11002.13,1726.78 h64.57
  text "g" at 11033.45,1726.75 h64.57
  text "P" at 11263.74,1724.02 h68.37
  text "P" at 11295.06,1724.02 h68.37
  text "(" at 11326.39,1724.02 h68.37
  text "1" at 11345.97,1724.02 h68.37
  text "0" at 11373.38,1724.02 h68.37
  text "8" at 11400.79,1724.02 h68.37
  text "0" at 11428.21,1724.02 h68.37
  text ")" at 11455.62,1724.02 h68.37
  text "R" at 11475.2,1724.02 h68.37
  text "C" at 11506.52,1724.02 h68.37
  text "7" at 11537.85,1724.02 h68.37
  text "1" at 11565.26,1724.02 h68.37
  text "3" at 11764.03,1724.02 h68.37
  text "." at 11791.45,1724.02 h68.37
  text "9" at 11807.11,1724.02 h68.37
  text "3" at 12088.45,1724.02 h68.37
  text "." at 12115.86,1724.02 h68.37
  text "7" at 12131.52,1724.02 h68.37
  text "4" at 12158.93,1724.02 h68.37
  text "1" at 9876.19,1648.46 h64.57
  text "2" at 9907.52,1648.46 h64.57
  text "L" at 10071.62,1648.46 h64.57
  text "8" at 10102.95,1648.46 h64.57
  text "-" at 10134.28,1648.5 h64.57
  text "B" at 10153.86,1648.46 h64.57
  text "O" at 10193.02,1648.46 h64.57
  text "T" at 10240.01,1648.46 h64.57
  text "G" at 10626.64,1648.46 h64.57
  text "B" at 10669.71,1648.46 h64.57
  text "L" at 10708.87,1648.46 h64.57
  text "C" at 10861.15,1648.46 h64.57
  text "o" at 10904.23,1648.46 h64.57
  text "p" at 10935.56,1648.43 h64.57
  text "p" at 10966.88,1648.43 h64.57
  text "e" at 10998.21,1648.46 h64.57
  text "r" at 11029.54,1648.46 h64.57
  text "0" at 12100.17,1645.7 h68.37
  text "." at 12127.58,1645.7 h68.37
  text "7" at 12143.25,1645.7 h68.37
  text "1" at 12350.32,1645.7 h68.37
  text "/" at 12377.73,1645.7 h68.37
  text "3" at 12401.23,1645.7 h68.37
  text "+" at 12440.39,1645.7 h68.37
  text "p" at 12479.55,1645.7 h68.37
  text "l" at 12510.87,1645.7 h68.37
  text "a" at 12526.54,1645.7 h68.37
  text "t" at 12553.95,1645.7 h68.37
  text "i" at 12573.53,1645.7 h68.37
  text "n" at 12589.19,1645.7 h68.37
  text "g" at 12620.52,1645.7 h68.37
  text "5" at 12881.89,1645.7 h68.37
  text "0" at 12909.3,1645.7 h68.37
  text "4" at 13225.84,1645.7 h68.37
  text "." at 13253.25,1645.7 h68.37
  text "5" at 13268.92,1645.7 h68.37
  text "0" at 13296.33,1645.7 h68.37
  text "L" at 13612.79,1645.7 h68.37
  text "7" at 13636.29,1645.7 h68.37
  text "1" at 13972.38,1645.7 h68.37
  text "0" at 13999.79,1645.7 h68.37
  text "0" at 14027.2,1645.7 h68.37
  text "4" at 14214.71,1645.7 h68.37
  text "." at 14242.12,1645.7 h68.37
  text "2" at 14257.79,1645.7 h68.37
  text "0" at 14285.2,1645.7 h68.37
  text "/" at 14324.36,1645.7 h68.37
  text "8" at 14359.6,1645.7 h68.37
  text "." at 14387.01,1645.7 h68.37
  text "4" at 14402.68,1645.7 h68.37
  text "0" at 14430.09,1645.7 h68.37
  text "L" at 14664.2,1645.7 h68.37
  text "7" at 14687.69,1645.7 h68.37
  text "S" at 10071.62,1570.14 h64.57
  text "o" at 10110.78,1570.14 h64.57
  text "l" at 10142.11,1570.14 h64.57
  text "d" at 10153.86,1570.14 h64.57
  text "e" at 10185.18,1570.14 h64.57
  text "r" at 10216.51,1570.14 h64.57
  text "M" at 10251.75,1570.14 h64.57
  text "a" at 10294.83,1570.14 h64.57
  text "s" at 10326.16,1570.14 h64.57
  text "k" at 10357.48,1570.14 h64.57
  text "B" at 10400.56,1570.14 h64.57
  text "o" at 10439.72,1570.14 h64.57
  text "t" at 10471.05,1570.14 h64.57
  text "t" at 10486.71,1570.14 h64.57
  text "o" at 10502.37,1570.14 h64.57
  text "m" at 10533.7,1570.14 h64.57
  text "G" at 10626.64,1570.14 h64.57
  text "B" at 10669.71,1570.14 h64.57
  text "S" at 10708.87,1570.14 h64.57
  text "S" at 10861.15,1570.14 h64.57
  text "o" at 10900.31,1570.14 h64.57
  text "l" at 10931.64,1570.14 h64.57
  text "d" at 10943.39,1570.14 h64.57
  text "e" at 10974.72,1570.14 h64.57
  text "r" at 11006.04,1570.14 h64.57
  text "R" at 11041.29,1570.14 h64.57
  text "e" at 11084.36,1570.14 h64.57
  text "s" at 11115.69,1570.14 h64.57
  text "i" at 11147.02,1570.14 h64.57
  text "s" at 11158.76,1570.14 h64.57
  text "t" at 11190.09,1570.14 h64.57
  text "3" at 11764.03,1567.38 h68.37
  text "." at 11791.45,1567.38 h68.37
  text "5" at 11807.11,1567.38 h68.37
  text "O" at 10071.62,1491.82 h64.57
  text "v" at 10118.61,1491.82 h64.57
  text "e" at 10146.02,1491.82 h64.57
  text "r" at 10177.35,1491.82 h64.57
  text "l" at 10196.93,1491.82 h64.57
  text "a" at 10208.68,1491.82 h64.57
  text "y" at 10240.01,1491.79 h64.57
  text "B" at 10283.08,1491.82 h64.57
  text "o" at 10322.24,1491.82 h64.57
  text "t" at 10353.57,1491.82 h64.57
  text "t" at 10369.23,1491.82 h64.57
  text "o" at 10384.9,1491.82 h64.57
  text "m" at 10416.22,1491.82 h64.57
  text "G" at 10626.64,1491.82 h64.57
  text "B" at 10669.71,1491.82 h64.57
  text "O" at 10708.87,1491.82 h64.57
  text "S" at 10861.15,1491.82 h64.57
  text "i" at 10900.31,1491.82 h64.57
  text "l" at 10912.06,1491.82 h64.57
  text "k" at 10923.81,1491.82 h64.57
  text "s" at 10951.22,1491.82 h64.57
  text "c" at 10982.55,1491.82 h64.57
  text "r" at 11013.88,1491.82 h64.57
  text "e" at 11033.45,1491.82 h64.57
  text "e" at 11064.78,1491.82 h64.57
  text "n" at 11096.11,1491.82 h64.57
Assy Notes Top:
  text "NOTES /  / 1. SOLDER QSFP1 AND QSFP2 IN EIGHT PLACES ON BOTTOM SIDE AS INDICATED. /  / 2. KEEP SO1-SO4 CLEAN AND CLEAR OF SOLDER PASTE. /  / 3. JSO1-JSO4 ARE PRESS-FIT ATTACHED TO THE PCB. THE MATING JSO HARDWARE MUST BE ATTACHED TO THE PRESS-FIT PIECE AFTER ASSEMBLY. /  / 4. AFTER SMT ASSEMBLY, ATTACH STANDOFF SO4 USING M2.5 SCREW (OPAL KELLY P/N 001811) AND NUT (OPAL KELLY P/N 001810)." at -104,3129 h50
Assy Notes Bot:
  circle w10: c7192.9,1889.76 r74.01
  circle w10: c7192.91,866.14 r74.01
  circle w10: c8677.15,1889.76 r74.01
  circle w10: c8854.31,1141.73 r74.01
  circle w10: c8854.33,118.11 r74.01
  circle w10: c8677.17,866.14 r74.01
  circle w10: c7370.06,1141.73 r74.01
  circle w10: c7370.08,118.11 r74.01
  lines w10: 8726.87,1830.61 8811.87,1745.61 9092.07,1745.61
  text "SOLDER ON BOTTOM SIDE / (8 PLACES)" at 10169.29,1484.25 h60
Drill Drawing:
  drawing of 154 lines, arcs and shapes, not listed
  text "DRILL TABLE" at 8866.14,6299.21 h50
  text "Symbol" at 8898.83,6181.87 h60
  text "Count" at 9319.33,6181.87 h60
  text "Hole Size" at 9868.51,6181.87 h60
  text "Plated" at 10834.23,6181.87 h60
  text "Hole Type" at 11254.72,6181.87 h60
  text "Drill Layer Pair" at 11865.16,6181.87 h60
  text "Via/Pad" at 12855.47,6181.87 h60
  text "Hole Tolerance" at 13345.95,6181.87 h60
  text "Hole Length" at 14246.29,6181.87 h60
  text "2032" at 9319.33,6056.87 h50
  text "10.00mil (0.254mm)" at 9868.51,6056.87 h50
  text "PTH" at 10834.23,6056.87 h50
  text "Round" at 11254.72,6056.87 h50
  text "L1-TOP - L8-BOT" at 11865.16,6056.87 h50
  text "Via" at 12855.47,6056.87 h50
  text "+/-3.00mil" at 13345.95,6056.87 h50
  text "-" at 14246.29,6056.87 h50
  text "206" at 9319.33,5931.87 h50
  text "31.50mil (0.800mm)" at 9868.51,5931.87 h50
  text "PTH" at 10834.23,5931.87 h50
  text "Round" at 11254.72,5931.87 h50
  text "L1-TOP - L8-BOT" at 11865.16,5931.87 h50
  text "Pad" at 12855.47,5931.87 h50
  text "+/-3.00mil" at 13345.95,5931.87 h50
  text "-" at 14246.29,5931.87 h50
  text "F" at 8874.82,5923.88 h55.56
  text "18" at 9319.33,5806.87 h50
  text "40.16mil (1.020mm)" at 9868.51,5806.87 h50
  text "NPTH" at 10834.23,5806.87 h50
  text "Round" at 11254.72,5806.87 h50
  text "L1-TOP - L8-BOT" at 11865.16,5806.87 h50
  text "Pad" at 12855.47,5806.87 h50
  text "+/-3.00mil" at 13345.95,5806.87 h50
  text "-" at 14246.29,5806.87 h50
  text "E" at 8874.82,5798.88 h55.56
  text "2" at 9319.33,5681.87 h50
  text "41.34mil (1.050mm)" at 9868.51,5681.87 h50
  text "NPTH" at 10834.23,5681.87 h50
  text "Round" at 11254.72,5681.87 h50
  text "L1-TOP - L8-BOT" at 11865.16,5681.87 h50
  text "Pad" at 12855.47,5681.87 h50
  text "+/-3.00mil" at 13345.95,5681.87 h50
  text "-" at 14246.29,5681.87 h50
  text "22" at 9319.33,5556.87 h50
  text "41.34mil (1.050mm)" at 9868.51,5556.87 h50
  text "PTH" at 10834.23,5556.87 h50
  text "Round" at 11254.72,5556.87 h50
  text "L1-TOP - L8-BOT" at 11865.16,5556.87 h50
  text "Pad" at 12855.47,5556.87 h50
  text "+/-3.00mil" at 13345.95,5556.87 h50
  text "-" at 14246.29,5556.87 h50
  text "1" at 9319.33,5431.87 h50
  text "43.31mil (1.100mm)" at 9868.51,5431.87 h50
  text "NPTH" at 10834.23,5431.87 h50
  text "Round" at 11254.72,5431.87 h50
  text "L1-TOP - L8-BOT" at 11865.16,5431.87 h50
  text "Pad" at 12855.47,5431.87 h50
  text "+/-3.00mil" at 13345.95,5431.87 h50
  text "-" at 14246.29,5431.87 h50
  text "4" at 9319.33,5306.87 h50
  text "53.15mil (1.350mm)" at 9868.51,5306.87 h50
  text "PTH" at 10834.23,5306.87 h50
  text "Round" at 11254.72,5306.87 h50
  text "L1-TOP - L8-BOT" at 11865.16,5306.87 h50
  text "Pad" at 12855.47,5306.87 h50
  text "+/-3.00mil" at 13345.95,5306.87 h50
  text "-" at 14246.29,5306.87 h50
  text "8" at 9319.33,5181.87 h50
  text "59.00mil (1.499mm)" at 9868.51,5181.87 h50
  text "PTH" at 10834.23,5181.87 h50
  text "Round" at 11254.72,5181.87 h50
  text "L1-TOP - L8-BOT" at 11865.16,5181.87 h50
  text "Pad" at 12855.47,5181.87 h50
  text "+/-3.00mil" at 13345.95,5181.87 h50
  text "-" at 14246.29,5181.87 h50
  text "3" at 9319.33,5056.87 h50
  text "59.06mil (1.500mm)" at 9868.51,5056.87 h50
  text "PTH" at 10834.23,5056.87 h50
  text "Round" at 11254.72,5056.87 h50
  text "L1-TOP - L8-BOT" at 11865.16,5056.87 h50
  text "Pad" at 12855.47,5056.87 h50
  text "+/-3.00mil" at 13345.95,5056.87 h50
  text "-" at 14246.29,5056.87 h50
  text "4" at 9319.33,4931.87 h50
  text "61.02mil (1.550mm)" at 9868.51,4931.87 h50
  text "NPTH" at 10834.23,4931.87 h50
  text "Round" at 11254.72,4931.87 h50
  text "L1-TOP - L8-BOT" at 11865.16,4931.87 h50
  text "Pad" at 12855.47,4931.87 h50
  text "+/-3.00mil" at 13345.95,4931.87 h50
  text "-" at 14246.29,4931.87 h50
  text "1" at 9319.33,4806.87 h50
  text "62.99mil (1.600mm)" at 9868.51,4806.87 h50
  text "NPTH" at 10834.23,4806.87 h50
  text "Round" at 11254.72,4806.87 h50
  text "L1-TOP - L8-BOT" at 11865.16,4806.87 h50
  text "Pad" at 12855.47,4806.87 h50
  text "+/-3.00mil" at 13345.95,4806.87 h50
  text "-" at 14246.29,4806.87 h50
  text "11" at 9319.33,4681.87 h50
  text "65.00mil (1.651mm)" at 9868.51,4681.87 h50
  text "PTH" at 10834.23,4681.87 h50
  text "Round" at 11254.72,4681.87 h50
  text "L1-TOP - L8-BOT" at 11865.16,4681.87 h50
  text "Pad" at 12855.47,4681.87 h50
  text "+/-3.00mil" at 13345.95,4681.87 h50
  text "-" at 14246.29,4681.87 h50
  text "32" at 9319.33,4556.87 h50
  text "67.00mil (1.702mm)" at 9868.51,4556.87 h50
  text "PTH" at 10834.23,4556.87 h50
  text "Round" at 11254.72,4556.87 h50
  text "L1-TOP - L8-BOT" at 11865.16,4556.87 h50
  text "Pad" at 12855.47,4556.87 h50
  text "+/-3.00mil" at 13345.95,4556.87 h50
  text "-" at 14246.29,4556.87 h50
  text "6" at 9319.33,4431.87 h50
  text "70.87mil (1.800mm)" at 9868.51,4431.87 h50
  text "PTH" at 10834.23,4431.87 h50
  text "Round" at 11254.72,4431.87 h50
  text "L1-TOP - L8-BOT" at 11865.16,4431.87 h50
  text "Pad" at 12855.47,4431.87 h50
  text "+/-3.00mil" at 13345.95,4431.87 h50
  text "-" at 14246.29,4431.87 h50
  text "2" at 9319.33,4306.87 h50
  text "118.11mil (3.000mm)" at 9868.51,4306.87 h50
  text "NPTH" at 10834.23,4306.87 h50
  text "Round" at 11254.72,4306.87 h50
  text "L1-TOP - L8-BOT" at 11865.16,4306.87 h50
  text "Pad" at 12855.47,4306.87 h50
  text "+/-3.00mil" at 13345.95,4306.87 h50
  text "-" at 14246.29,4306.87 h50
  text "18" at 9319.33,4181.87 h50
  text "125.98mil (3.200mm)" at 9868.51,4181.87 h50
  text "PTH" at 10834.23,4181.87 h50
  text "Round" at 11254.72,4181.87 h50
  text "L1-TOP - L8-BOT" at 11865.16,4181.87 h50
  text "Pad" at 12855.47,4181.87 h50
  text "+/-3.00mil" at 13345.95,4181.87 h50
  text "-" at 14246.29,4181.87 h50
  text "D" at 8874.82,4173.88 h55.56
  text "4" at 9319.33,4056.87 h50
  text "145.67mil (3.700mm)" at 9868.51,4056.87 h50
  text "PTH" at 10834.23,4056.87 h50
  text "Round" at 11254.72,4056.87 h50
  text "L1-TOP - L8-BOT" at 11865.16,4056.87 h50
  text "Pad" at 12855.47,4056.87 h50
  text "+/-3.00mil" at 13345.95,4056.87 h50
  text "-" at 14246.29,4056.87 h50
  text "4" at 9319.33,3931.87 h50
  text "250.00mil (6.350mm)" at 9868.51,3931.87 h50
  text "NPTH" at 10834.23,3931.87 h50
  text "Round" at 11254.72,3931.87 h50
  text "L1-TOP - L8-BOT" at 11865.16,3931.87 h50
  text "Pad" at 12855.47,3931.87 h50
  text "+/-3.00mil" at 13345.95,3931.87 h50
  text "-" at 14246.29,3931.87 h50
  text "G" at 8874.82,3923.88 h55.56
  text "2378 Total" at 9319.33,3806.87 h50
Doc-Assy-Top:
  lines w5.43: -574.46,-2438.53 -357.09,-2438.53 ; -574.46,-129 -357.09,-129 ; -574.46,2180.53 -357.09,2180.53 ; 2196.97,-4530.68 2196.97,-4313.32 ; 2196.97,4055.32 2196.97,4272.68 ; 5185.77,-4530.68 5185.77,-4313.32 ; 5185.77,4055.32 5185.77,4272.68 ; 6055.24,-4530.68 10946,-4530.68 ; 7472.11,-4313.02 7472.11,-3538.36 10727.73,-3538.36 ; 7472.11,-4051.6 10727.73,-4051.6 ; 7963.42,-4313.02 7963.42,-4051.6 ; 8174.57,-4530.68 8174.57,-4313.32 ; 8174.57,4055.32 8174.57,4272.68 ; 8725.66,-4313.02 8725.66,-4051.6 ; 8878.06,-4051.27 8878.06,-3538.36 ; 9852.45,-4313.02 9852.45,-4051.6 ; 10728.63,-2438.53 10946,-2438.53 ; 10728.63,-129 10946,-129 ; 10728.63,2180.53 10946,2180.53 ; 10946,-4530.68 -574.46,-4530.68 -574.46,4272.68 10946,4272.68 10946,-4530.68 ; -357.09,-4313.32 10728.63,-4313.32 10728.63,4055.32 -357.09,4055.32 -357.09,-4313.32
  text "1" at 676.86,4129.38 h76.08
  text "2" at 3666.38,4129.38 h76.08
  text "3" at 6649.74,4129.38 h76.08
  text "4" at 9639.64,4129.38 h76.08
  text "A" at -496.37,3236.93 h76.08
  text "A" at 10813.57,3236.93 h76.08
  text "B" at -496.37,927.4 h76.08
  text "B" at 10813.57,927.4 h76.08
  text "C" at -496.37,-1382.12 h76.08
  text "C" at 10813.57,-1382.12 h76.08
  text "TITLE:" at 7556.48,-3623.9 h48.89
  text "Opal Kelly" at 8963.6,-3658.12 h76.04
  text "D" at -496.37,-3686.21 h76.08
  text "D" at 10813.57,-3686.21 h76.08
  text "13500 SW 72nd Ave Suite 100" at 8963.6,-3786.43 h76.04
  text "Portland, OR 97223" at 8963.6,-3893.35 h76.04
  text "'.Part_Number' / Assembly Drawing" at 7591.65,-3895.18 h76.04
  text "www.opalkelly.com" at 8963.6,-4000.28 h76.04
  text "(Top)" at 7591.65,-4019.03 h76.04
  text "REV:" at 7532.59,-4124.03 h48.89
  text "SIZE:" at 8029.7,-4124.03 h48.89
  text "ENGINEER:" at 8791.94,-4124.03 h48.89
  text "DATE:" at 9918.73,-4124.03 h48.89
  text "'.PCB_Revision'XX" at 7598.87,-4256.6 h76.04
  text "ANSI A" at 8095.98,-4256.6 h76.04
  text "RCA" at 8858.22,-4256.6 h76.04
  text ".PRINT_DATE" at 9985.01,-4256.6 h76.04
  text "1" at 676.86,-4463.46 h76.08
  text "2" at 3666.38,-4463.46 h76.08
  text "3" at 6649.74,-4463.46 h76.08
  text "4" at 9639.64,-4463.46 h76.08
Doc-Assy-Bot:
  lines w5.43: -574.34,-2437.51 -356.97,-2437.51 ; -574.34,-127.94 -356.97,-127.94 ; -574.34,2181.64 -356.97,2181.64 ; -356.07,-4050.62 2899.62,-4050.62 ; -356.07,-3537.38 2899.62,-3537.38 2899.62,-4312.05 ; 519.24,-4312.05 519.24,-4050.62 ; 1493.65,-4050.3 1493.65,-3537.38 ; 1646.05,-4312.05 1646.05,-4050.62 ; 2197.15,-4529.72 2197.15,-4312.35 ; 2197.15,4056.47 2197.15,4273.84 ; 2408.31,-4312.05 2408.31,-4050.62 ; 4316.53,-4529.72 -574.34,-4529.72 ; 5186.02,-4529.72 5186.02,-4312.35 ; 5186.02,4056.47 5186.02,4273.84 ; 8174.88,-4529.72 8174.88,-4312.35 ; 8174.88,4056.47 8174.88,4273.84 ; 10729,-2437.51 10946.37,-2437.51 ; 10729,-127.94 10946.37,-127.94 ; 10729,2181.64 10946.37,2181.64 ; -574.34,-4529.72 -574.34,4273.84 10946.37,4273.84 10946.37,-4529.72 -574.34,-4529.72 ; -356.97,-4312.35 -356.97,4056.47 10729,4056.47 10729,-4312.35 -356.97,-4312.35
  text "4" at 732.05,4130.54 h76.08
  text "3" at 3722.02,4130.54 h76.08
  text "2" at 6705.45,4130.54 h76.08
  text "1" at 9695.03,4130.54 h76.08
  text "A" at -441.9,3238.07 h76.08
  text "A" at 10868.28,3238.07 h76.08
  text "B" at -441.9,928.49 h76.08
  text "B" at 10868.28,928.49 h76.08
  text "C" at -441.9,-1381.09 h76.08
  text "C" at 10868.28,-1381.09 h76.08
  text "TITLE:" at 2815.25,-3622.92 h48.89
  text "Opal Kelly" at 1408.11,-3657.13 h76.05
  text "D" at -441.9,-3685.23 h76.08
  text "D" at 10868.28,-3685.23 h76.08
  text "13500 SW 72nd Ave Suite 100" at 1408.11,-3785.44 h76.05
  text "Portland, OR 97223" at 1408.11,-3892.37 h76.05
  text "'.Part_Number' / Assembly Drawing" at 2780.09,-3894.2 h76.05
  text "www.opalkelly.com" at 1408.11,-3999.3 h76.05
  text "(Bottom)" at 2780.09,-4018.05 h76.05
  text "DATE:" at 452.95,-4123.06 h48.89
  text "ENGINEER:" at 1579.77,-4123.06 h48.89
  text "SIZE:" at 2342.03,-4123.06 h48.89
  text "REV:" at 2839.15,-4123.06 h48.89
  text ".PRINT_DATE" at 386.67,-4255.63 h76.05
  text "RCA" at 1513.49,-4255.63 h76.05
  text "ANSI A" at 2275.74,-4255.63 h76.05
  text "'.PCB_Revision'XX" at 2772.87,-4255.63 h76.05
  text "4" at 732.05,-4462.5 h76.08
  text "3" at 3722.02,-4462.5 h76.08
  text "2" at 6705.45,-4462.5 h76.08
  text "1" at 9695.03,-4462.5 h76.08
Doc-Fab:
  lines w5: 10771,-3272.14 10771,-2216 15310.19,-2216 ; 10771,-3165.89 12531,-3165.89 ; 10771,-3048.89 12531,-3048.89 ; 10771,-2931.89 12531,-2931.89 ; 10771,-2788.01 12531,-2788.01 ; 10771,-2671.01 12531,-2671.01 ; 10771,-2554.01 12531,-2554.01 ; 10771,-2406 12531,-2406 ; 10771,-2296 12531,-2296 ; 11191,-3272.14 11191,-2216 ; 12531,-3272.14 12531,-2216 ; 12531,-3076 15311,-3076 ; 12531,-2636 15310.19,-2636 ; 13091,-3272.14 13091,-3076 ; 13771,-3076 13771,-2636 ; 14421,-3272.14 14421,-3076
  lines w5.49: -952.83,-883.82 -733.05,-883.82 ; -952.83,1726.12 -733.05,1726.12 ; -952.83,4336.06 -733.05,4336.06 ; 1794.47,-3493.76 1794.47,-3273.97 ; 1794.47,6726.22 1794.47,6946 ; 4541.78,-3493.76 4541.78,-3273.97 ; 4541.78,6726.22 4541.78,6946 ; 7289.08,-3493.76 7289.08,-3273.97 ; 7289.08,6726.22 7289.08,6946 ; 10036.39,-3493.76 10036.39,-3273.97 ; 10036.39,6726.22 10036.39,6946 ; 12783.69,-3493.76 12783.69,-3273.97 ; 12783.69,6726.22 12783.69,6946 ; 15311.22,-883.82 15531,-883.82 ; 15311.22,1726.12 15531,1726.12 ; 15311.22,4336.06 15531,4336.06 ; -952.83,-3493.76 15531,-3493.76 15531,6946 -952.83,6946 -952.83,-3493.76 ; -733.05,-3273.97 15311.22,-3273.97 15311.22,6726.22 -733.05,6726.22 -733.05,-3273.97
  text "1" at 400.31,6803.14 h76.92
  text "2" at 3142.85,6803.14 h76.92
  text "3" at 5878.45,6803.14 h76.92
  text "4" at 8633.08,6803.14 h76.92
  text "5" at 11379.27,6803.14 h76.92
  text "6" at 14132.07,6803.14 h76.92
  text "A" at -870.41,5547.07 h76.92
  text "A" at 15393.63,5547.07 h76.92
  text "B" at -870.41,2931.64 h76.92
  text "B" at 15393.63,2931.64 h76.92
  text "C" at -870.41,321.7 h76.92
  text "C" at 15393.63,321.7 h76.92
  text "REVISION:" at 10800,-2276 h40
  text "DESCRIPTION:" at 11230,-2276 h40
  text "D" at -870.41,-2282.75 h76.92
  text "D" at 15393.63,-2282.75 h76.92
  text "PART NUMBER:" at 12611,-2356 h75
  text "AXX" at 10801,-2376 h50
  text "Initial Release" at 11231,-2376 h50
  text "BXX" at 10801,-2486 h50
  text "Added solder paste apertures to M.2 connector footprint" at 11224.41,-2555.12 h35
  text "CXX" at 10801,-2634.01 h50
  text "'.Part_Number'-PCB-'.PCB_Revision'XX" at 12631,-2636 h130
  text "Updates for new XEM8350 outline" at 11224.41,-2656.67 h50
  text "TITLE:" at 12591,-2716 h40
  text "Opal Kelly" at 13831,-2736 h60
  text "DXX" at 10801,-2751.01 h50
  text "Updated TXR-2 ports to TXR-4" at 11225,-2773.67 h50
  text "13500 SW 72nd Ave Suite 100" at 13831,-2836 h60
  text "EXX" at 10802,-2867.91 h50
  text "Updated QSFP mtg holes to non-plated, updated U3 gnd planes" at 11224.41,-2933.07 h35
  text "Portland, OR 97223" at 13831,-2936 h60
  text "FXX" at 10801,-3011.89 h50
  text "'.Part_Number' / Fabrication Drawing" at 12631,-3016 h60
  text "Reverse QSFP TX channel order" at 11225,-3034.55 h50
  text "www.opalkelly.com" at 13831,-3036 h60
  text "GXX" at 10801,-3128.89 h50
  text "SIZE:" at 12591,-3136 h40
  text "ENGINEER:" at 13151,-3136 h40
  text "DATE:" at 14471,-3136 h40
  text "ECO-10123" at 11225,-3151.55 h50
  text "ANSI A" at 12631,-3236 h60
  text "RCA" at 13191,-3236 h60
  text ".PRINT_DATE" at 14511,-3236 h60
  text "HXX" at 10800.41,-3241.12 h50
  text "Transceiver signal integrity improvments" at 11224.41,-3255.91 h40
  text "1" at 400.31,-3416.83 h76.92
  text "2" at 3142.85,-3416.83 h76.92
  text "3" at 5878.45,-3416.83 h76.92
  text "4" at 8633.08,-3416.83 h76.92
  text "5" at 11379.27,-3416.83 h76.92
  text "6" at 14132.07,-3416.83 h76.92

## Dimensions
0,2952.76 to 9448.82,2952.76 on Dimensions
0,-2952.76 to 9251.97,2755.91 on Dimensions
0,-2952.76 to 196.85,2755.91 on Dimensions
0,-2952.76 to 196.85,2755.91 on Dimensions
196.85,-2755.91 to 0,-2952.76 on Dimensions
0,-2952.76 to 0,2952.76 on Dimensions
